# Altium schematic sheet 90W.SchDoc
size A2; SheetNumber: 0; SheetTotal: 0; PageSetup: Record=PageOptions|CenterHorizontal=True|CenterVertical=True|PrintScale=0.50|XCorrection=1.00|YCorrection=1.00|PrintKind=0|BorderSize=5000000|LeftOffset=0|BottomOffset=0|Orientation=2|PaperLength=1000|PaperWidth=1000|Scale=100|PaperSource=7|PrintQuality=-4|MediaType=1|DitherType=10|PaperKind=A4|PrintScaleMode=1
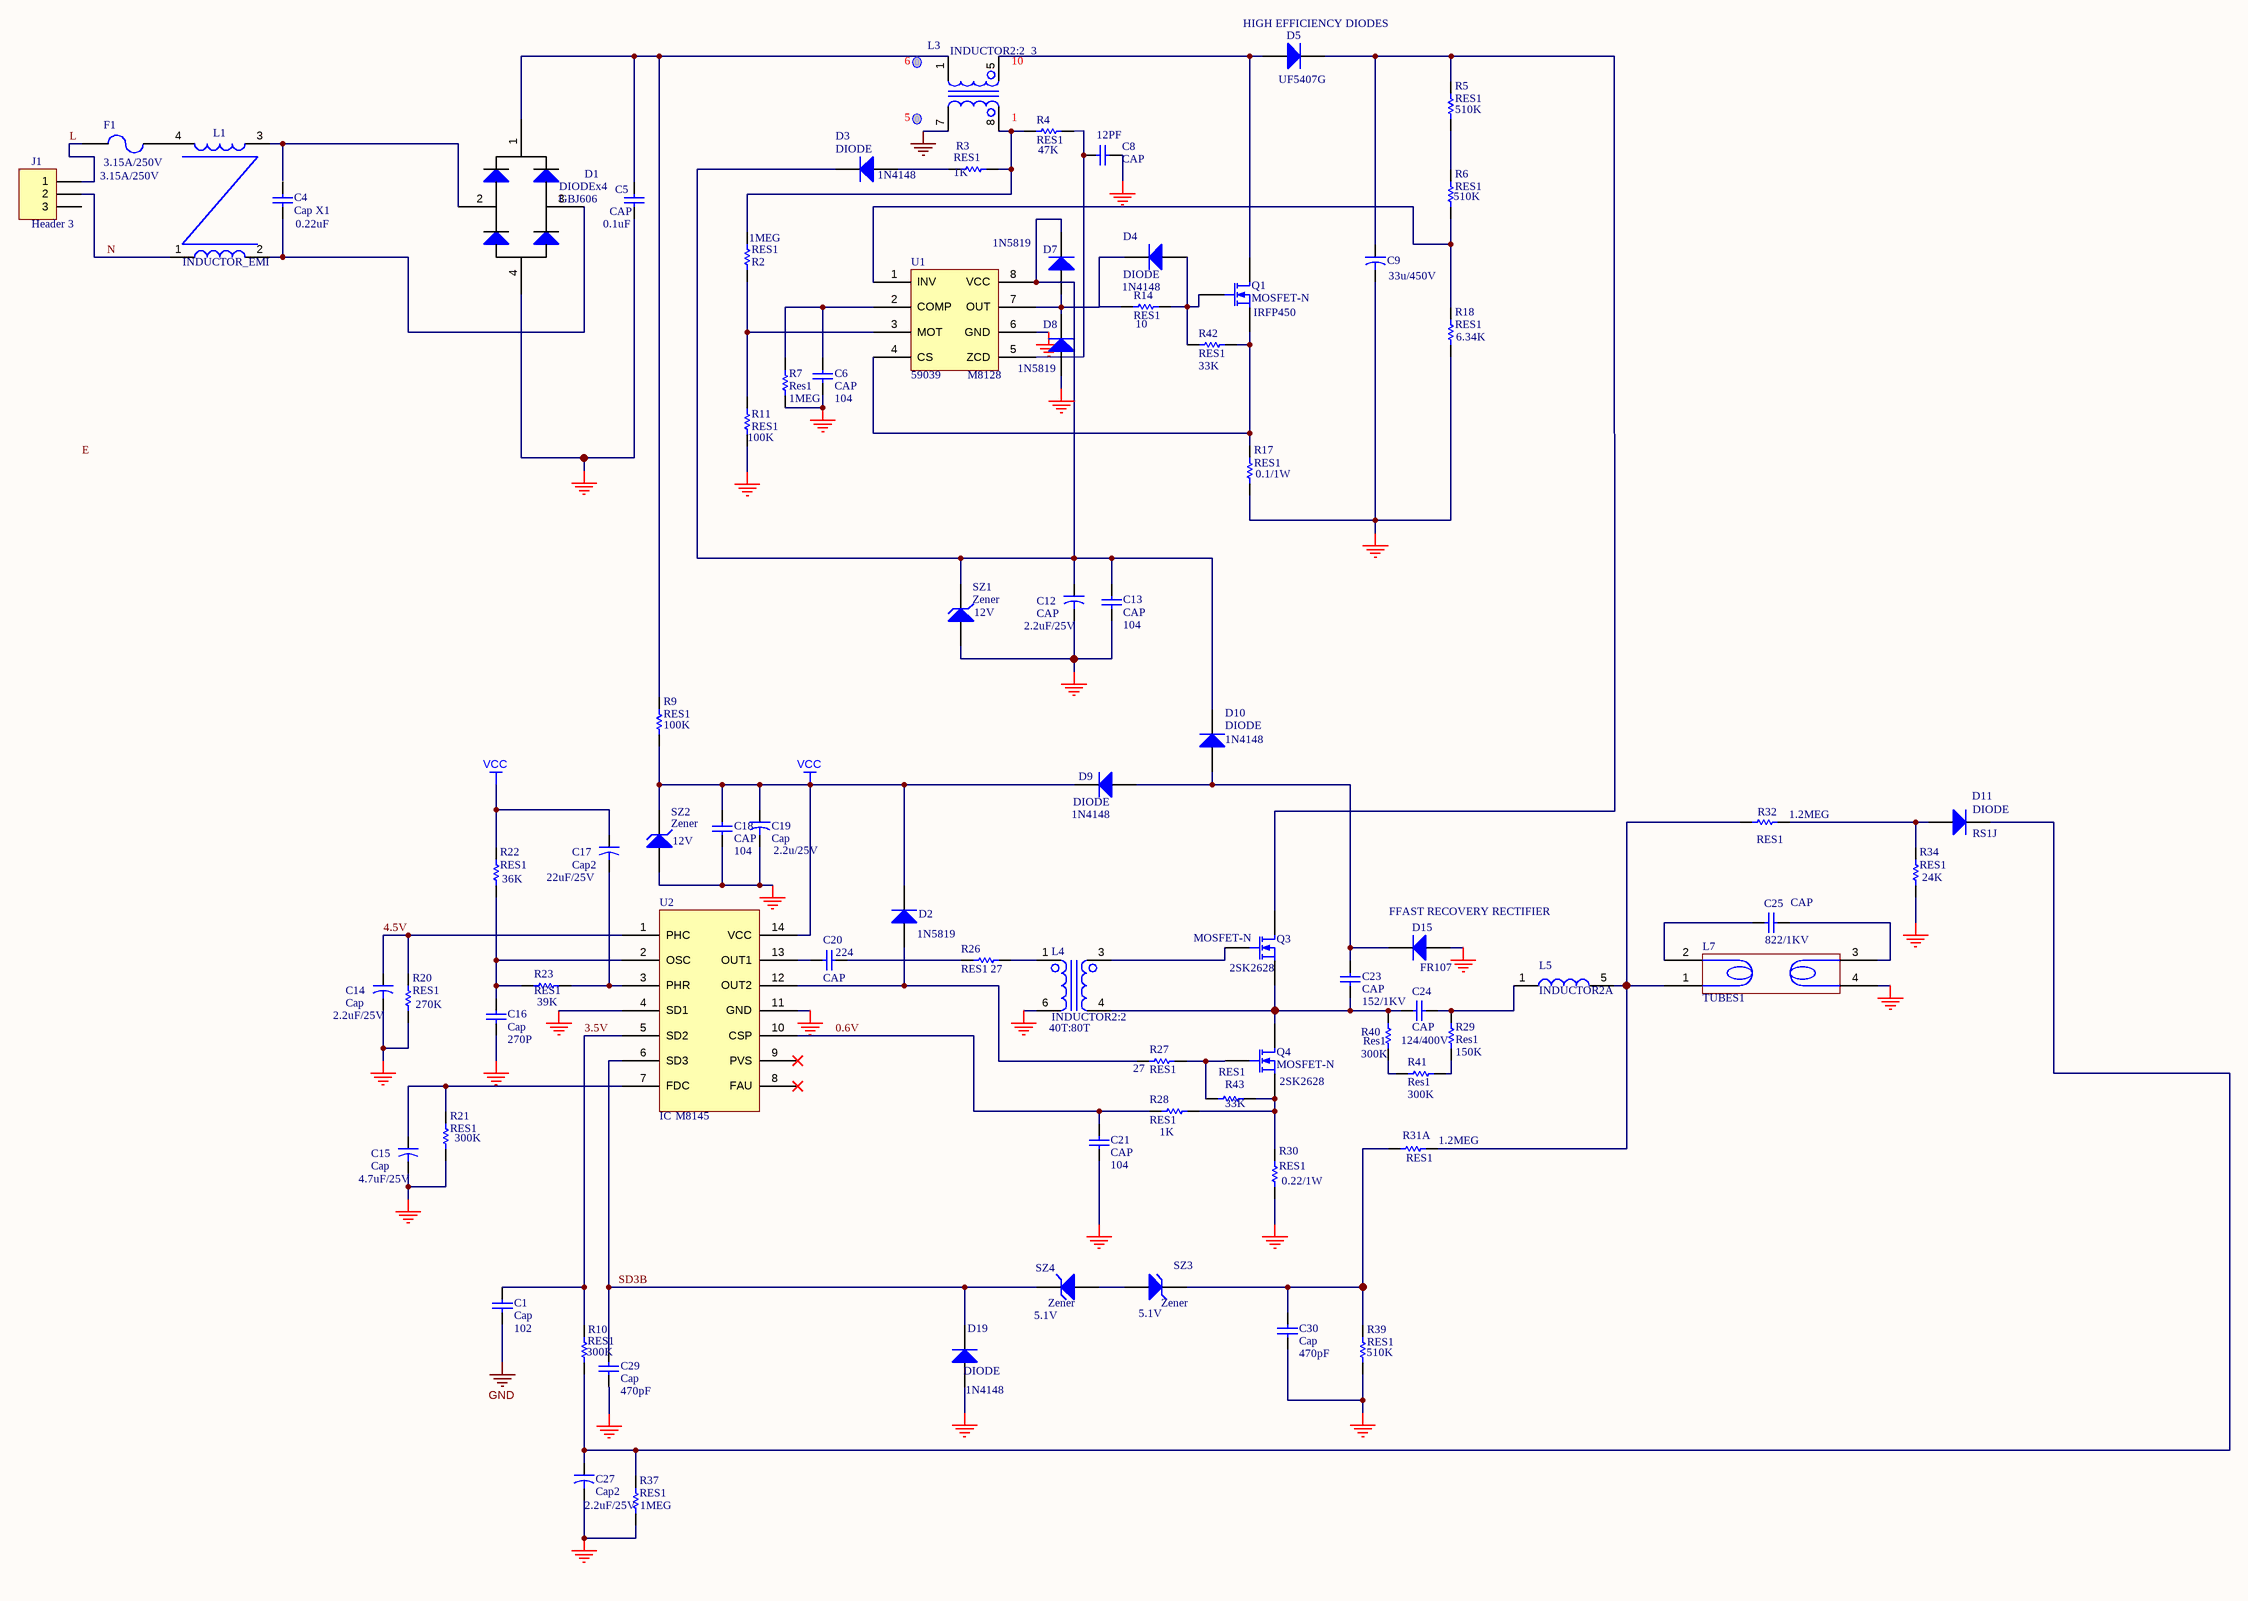
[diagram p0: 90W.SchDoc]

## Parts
C1  Cap  value 102  [C0805A]
C4  Cap X1  value 0.22uF  [RAD0.6B]
C5  CAP  value 0.1uF  [RAD0.6B]
C6  CAP  value 104  [RAD0.2B]
C8  CAP  value 12PF  [C0805A]
C9  value 33u/450V  [RB.3/.6A]  (hidden comment: Cap2)
C12  CAP  value 2.2uF/25V  [RB.2/.2]
C13  CAP  value 104  [C0805A]
C14  Cap  value 2.2uF/25V  [RB.2/.2]
C15  Cap  value 4.7uF/25V  [RB.2/.2]
C16  Cap  value 270P  [C0805A]
C17  Cap2  value 22uF/25V  [RB.2/.2]
C18  CAP  value 104  [RAD0.2B]
C19  Cap  value 2.2u/25V  [RB.2/.2]
C20  CAP  value 224  [C0805A]
C21  CAP  value 104  [C0805A]
C23  CAP  value 152/1KV  [RAD-0.3]
C24  CAP  value 124/400V  [RAD0.6A]
C25  CAP  value 822/1KV  [RAD0.6A]
C27  Cap2  value 2.2uF/25V  [RB.2/.2]
C29  Cap  value 470pF  [C0805A]
C30  Cap  value 470pF  [C0805A]
D1  DIODEx4  value GBJ606  [SIP4B]
D2  value 1N5819  [DO-41]  (hidden comment: Diode 1N5819)
D3  DIODE  value 1N4148  [CD3216-1206A]
D4  DIODE  value 1N4148  [CD3216-1206A]
D5  HIGH EFFICIENCY DIODES  value UF5407G  [DIODE0.7A]
D7  value 1N5819  [DO-41]  (hidden comment: Diode 1N5819)
D8  value 1N5819  [DO-41]  (hidden comment: Diode 1N5819)
D9  DIODE  value 1N4148  [CD3216-1206A]
D10  DIODE  value 1N4148  [CD3216-1206A]
D11  DIODE  value RS1J  [CD4532-1810]
D15  FFAST RECOVERY RECTIFIER  value FR107  [DIODE-0.4]
D19  DIODE  value 1N4148  [CD3216-1206A]
F1  3.15A/250V  [FUSE0.6]
J1  Header 3  [IDC6C]
L1  INDUCTOR_EMI  [EE1916H_EMI]
L3  INDUCTOR2:2_3  [EE25_PFC8]
L4  INDUCTOR2:2  value 40T:80T  [EE0808]
L5  INDUCTOR2A  [EE2520_LRES8]
L7  TUBES1  [IDC14-MIN]
Q1  MOSFET-N  value IRFP450  [TO-220B]
Q3  MOSFET-N  value 2SK2628  [TO-220B]
Q4  MOSFET-N  value 2SK2628  [TO-220B]
R2  RES1  value 1MEG  [2012[0805]A]
R3  RES1  value 1K  [2012[0805]A]
R4  RES1  value 47K  [2012[0805]A]
R5  RES1  value 510K  [2012[0805]A]
R6  RES1  value 510K  [2012[0805]A]
R7  Res1  value 1MEG  [2012[0805]A]
R9  RES1  value 100K  [2012[0805]A]
R10  RES1  value 300K  [2012[0805]A]
R11  RES1  value 100K  [2012[0805]A]
R14  RES1  value 10  [2012[0805]A]
R17  RES1  value 0.1/1W  [AXIAL-0.5]
R18  RES1  value 6.34K  [2012[0805]A]
R20  RES1  value 270K  [2012[0805]A]
R21  RES1  value 300K  [2012[0805]A]
R22  RES1  value 36K  [2012[0805]A]
R23  RES1  value 39K  [2012[0805]A]
R26  RES1  value 27  [2012[0805]A]
R27  RES1  value 27  [2012[0805]A]
R28  RES1  value 1K  [2012[0805]A]
R29  Res1  value 150K  [2012[0805]A]
R30  RES1  value 0.22/1W  [AXIAL-0.5]
R31A  RES1  value 1.2MEG  [2012[0805]A]
R32  RES1  value 1.2MEG  [2012[0805]A]
R34  RES1  value 24K  [2012[0805]A]
R37  RES1  value 1MEG  [2012[0805]A]
R39  RES1  value 510K  [2012[0805]A]
R40  Res1  value 300K  [2012[0805]A]
R41  Res1  value 300K  [2012[0805]A]
R42  RES1  value 33K  [2012[0805]A]
R43  RES1  value 33K  [2012[0805]A]
SZ1  Zener  value 12V  [CD3216-1206A]
SZ2  Zener  value 12V  [CD3216-1206A]
SZ3  Zener  value 5.1V  [CD3216-1206A]
SZ4  Zener  value 5.1V  [CD3216-1206A]
U1  59039  value M8128  [DIP-8]
U2  IC  value M8145  [DIP-14]

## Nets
GND: C1.1 C5.1 C6.1 C8.2 C9.2 C12.2 C13.1 C14.2 C15.2 C16.1 C18.1 C19.2 C21.1 C27.2 C29.1 C30.2 D1.4 D8.1(A) D15.1(A) D19.1(A) L3.7 L4.6 L7.4(TR4) R7.1 R11.2 R17.1 R18.1 R20.1 R21.1 R30.1 R34.1 R37.1 R39.1 SZ1.1(A) SZ2.1(A) U1.6(GND) U2.4(SD1) U2.11(GND)
VCC: C17.1 C18.2 C19.1 D2.2(K) D9.2(K) R9.1 R22.2 SZ2.2(K) U2.14(VCC)
0.6V: C21.2 R28.2 U2.10(CSP)
3.5V: C1.2 R10.2 U2.5(SD2)
4.5V: C14.1 R20.2 U2.1(PHC)
L: F1.1 J1.1
N: J1.2 L1.1(TR5)
SD3B: C29.2 D19.2(K) SZ4.2(K) U2.6(SD3)
NetC4_1: C4.1 D1.3 L1.2(TR6)
NetC5_2: C5.2 D1.1 L3.1 R9.2
NetC6_2: C6.2 R7.2 U1.2(COMP)
NetC8_1: C8.1 R4.2 U1.5(ZCD)
NetC9_1: C9.1 D5.2(K) Q3.1(D) R5.2
NetC12_1: C12.1 C13.2 D3.2(K) D7.2(K) D10.2(K) SZ1.2(K) U1.8(VCC)
NetC15_1: C15.1 R21.2 U2.7(FDC)
NetC16_2: C16.2 R22.1 R23.1 U2.2(OSC)
NetC17_2: C17.2 R23.2 U2.3(PHR)
NetC20_1: C20.1 R26.2
NetC20_2: C20.2 U2.13(OUT1)
NetC23_1: C23.1 C24.2 L4.4 Q3.3(S) Q4.1(D) R40.1
NetC23_2: C23.2 D9.1(A) D10.1(A) D15.2(K)
NetC24_1: C24.1 L5.1 R29.1
NetC25_1: C25.1 L7.2(TR2)
NetC25_2: C25.2 L7.3
NetC27_1: C27.1 D11.2(K) R10.1 R37.2
NetC30_1: C30.1 R31A.1 R39.2 SZ3.2(K)
NetD1_2: D1.2 L1.3(TR5)
NetD2_1: D2.1(A) R27.1 U2.12(OUT2)
NetD3_1: D3.1(A) R3.2
NetD4_1: D4.1(A) Q1.2(G) R14.2 R42.1
NetD4_2: D4.2(K) D7.1(A) D8.2(K) U1.7(OUT)
NetD5_1: D5.1(A) L3.5 Q1.1(D)
NetD11_1: D11.1(A) R32.2 R34.2
NetF1_2: F1.2 L1.4(TR6)
NetL3_8: L3.8 R2.1 R3.1 R4.1
NetL4_1: L4.1 R26.1
NetL4_3: L4.3 Q3.2(G)
NetL5_5: L5.5 L7.1(TR1) R31A.2 R32.1
NetQ1_3: Q1.3(S) R17.2 R42.2 U1.4(CS)
NetQ4_2: Q4.2(G) R27.2 R43.1
NetQ4_3: Q4.3(S) R28.1 R30.2 R43.2
NetR2_2: R2.2 R11.1 U1.3(MOT)
NetR5_1: R5.1 R6.2
NetR6_1: R6.1 R18.2 U1.1(INV)
NetR29_2: R29.2 R41.1
NetR40_2: R40.2 R41.2
NetSZ3_1: SZ3.1(A) SZ4.1(A)

Not connected (* = marked no-connect by the designer): C4 2; J1 3; R14 1; U2 8(FAU)* 9(PVS)*

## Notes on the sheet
- (near L3) 6
- (near L3) 10
- 5
- 1
- Labels drawn without touching a wire or pin: E

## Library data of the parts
C1 C16 C29 C30 = Cap: Ceramic Capacitor
C4 C5 = CAP: BOX Capacitor
C6 C13 C18 C23 = CAP: MLCC Capacitor
C8 C20 C21 = CAP: Ceramic Capacitor
C9 C12 C14 C15 C17 C19 C27 = Cap2: Electrolytic Capacitor
C24 C25 = CAP: POLYPROPYLENE FILM Capacitor
D1 = DIODEx4: Bridge Diode
D2 D7 D8 = Diode 1N4007: 1 Amp General Purpose Rectifier
D3 D4 D9 D10 D19 = DIODE: Diode  75V,1A
D5 = DIODE: Diode HIGH EFFICIENCY RECTIFIERS 600V, 3A
D11 D15 = DIODE: Diode FAST RECOVERY RECTIFIER 700V,1A
F1 = FUSE2: Fuse
J1 = Header 3: Jumper Wire Pin spacing 5mm         235-403(2LG+1G); VALUE: ºÝ¤l
L1 = INDUCTOR_EMI: EE19H Inductor; VALUE: 16mH
L3 = INDUCTOR2:2_3: EE25 Inductor
L4 = INDUCTOR2:2: EE08 Inductor
L5 = INDUCTOR2A: EE25 Inductor
L7 = TUBES1: Jumper Wire Pin spacing 3.5mm    235-107/000-009; VALUE: LAMP
Q1 = MOSFET-N: Transistor, MOSFET  600V, 11A; PackageDocument: 1995/1996
Q3 Q4 = MOSFET-N: Transistor, MOSFET  600V, 6A; PackageDocument: 1995/1996
R2-R6 R9-R11 R14 R18 R20-R23 R26-R28 R31A R32 R34 R37 R39 R42 R43 = RES1: Resistor 1/4W
R7 R29 R40 R41 = Res1: Resistor 1/4W
R17 R30 = RES1: Resistor 1W
SZ1-SZ4 = D Zener: Zener Diode 1/2W
U1 = 59039: IC, PFC Driver
U2 = M8145: IC, Ballast Driver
